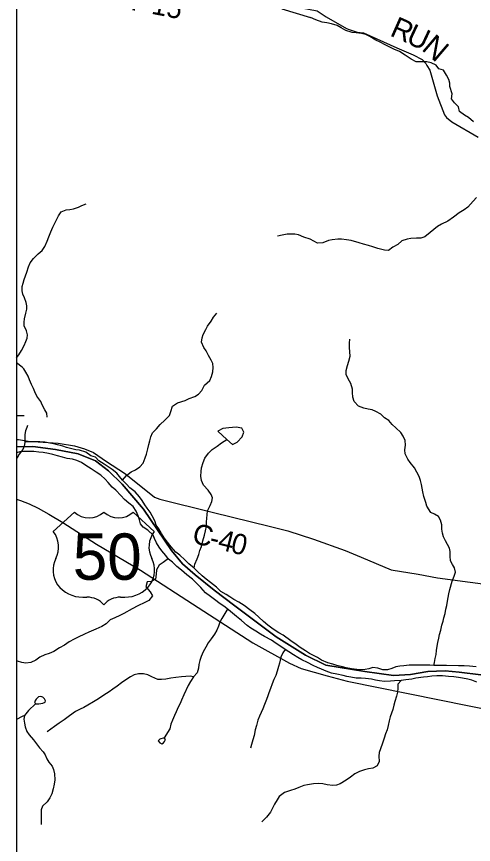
# Model space of a CAD drawing. Extents: x -139 to 835, y 0 to 440.
# Drawn here: x 373.2 to 414.4, y 270.4 to 344.8 of the extents above; entities that cross this region are included whole.
import ezdxf

# ---------------------------------------------------------------- set-up
doc = ezdxf.new("R2010")
doc.units = 0
for name, color, linetype in [('Default', 7, 'Continuous'), ('GM_X_County_Road', 7, 'Continuous'), ('GM_X_County_Road_Text', 7, 'Continuous'), ('GM_X_Major_River', 7, 'Continuous'), ('GM_X_Minor_Lake', 7, 'Continuous'), ('GM_X_Minor_River', 7, 'Continuous'), ('GM_X_Township_Road', 7, 'Continuous'), ('GM_X_Township_Road_Text', 7, 'Continuous'), ('GM_X_US_Location', 7, 'Continuous'), ('GM_X_US_Route', 7, 'Continuous'), ('GM_X_US_Shield', 7, 'Continuous'), ('SH_Cut_Line', 7, 'Continuous')]:
    doc.layers.add(name, color=color, linetype=linetype)

msp = doc.modelspace()

# ---------------------------------------------------------------- linework, layer by layer
at = {"layer": 'Default'}
for points in [[(373.24, 400.079), (373.24, 306.128), (374.696, 306.151), (376.756, 305.899), (378.796, 305.485), (380.346, 304.856), (381.503, 303.956), (382.739, 302.768), (384.674, 300.516), (387.19, 296.811), (388.165, 295.6), (389.313, 294.6), (391.035, 293.231), (392.871, 291.81), (396.601, 289.02), (399.241, 287.388), (401.077, 286.493), (404.578, 285.913), (407.16, 285.545), (408.709, 285.65), (410.258, 285.913), (411.808, 285.966), (413.07, 285.861), (415.021, 285.598)], [(415.021, 285.598), (413.07, 285.861), (411.808, 285.966), (410.258, 285.913), (408.709, 285.65), (407.16, 285.545), (404.578, 285.913), (401.077, 286.493), (399.241, 287.388), (396.601, 289.02), (392.871, 291.81), (391.035, 293.231), (389.313, 294.6), (388.165, 295.6), (387.19, 296.811), (384.674, 300.516), (382.739, 302.768), (381.503, 303.956), (380.346, 304.856), (378.796, 305.485), (376.756, 305.899), (374.696, 306.151), (373.24, 306.128), (373.24, 228.621)]]:
    msp.add_lwpolyline(points, dxfattribs=at)
at = {"layer": 'GM_X_County_Road'}
msp.add_lwpolyline([(373.24, 306.794), (373.416, 306.794), (374.294, 306.652), (376.981, 306.459), (378.441, 306.221), (379.352, 305.954), (380.168, 305.612), (381.334, 304.813), (382.959, 303.756), (384.566, 302.468), (385.652, 301.604), (386.129, 301.432), (390.834, 300.262), (396.089, 298.961), (397.653, 298.562), (399.969, 297.831), (402.806, 296.795), (404.254, 296.211), (406.971, 295.065), (409.385, 294.68), (411.116, 294.343), (416.995, 293.57)], dxfattribs=at)
at = {"layer": 'GM_X_Major_River'}
for points in [[(373.938, 308.918), (373.617, 308.91), (373.24, 308.915)], [(414.594, 286.329), (414.021, 286.384), (413.526, 286.414), (413.005, 286.432), (411.936, 286.446), (411.532, 286.451), (410.802, 286.46), (410.437, 286.476), (408.99, 286.494), (408.573, 286.476), (408.103, 286.434), (407.737, 286.378), (407.384, 286.323), (407.004, 286.195), (406.638, 286.068), (406.221, 286.073), (405.766, 286.199), (405.298, 286.265), (404.958, 286.161), (404.618, 286.094), (404.253, 286.074), (403.875, 286.079), (403.38, 286.158), (402.913, 286.248), (402.575, 286.324), (402.081, 286.462), (401.718, 286.563), (401.251, 286.701), (400.68, 286.924), (400.319, 287.157), (399.969, 287.342), (399.62, 287.538), (399.246, 287.783), (398.755, 288.077), (398.419, 288.346), (397.916, 288.664), (397.232, 289.177), (396.831, 289.398), (396.328, 289.729), (395.851, 290.095), (395.451, 290.401), (395.04, 290.802), (394.692, 291.119), (394.241, 291.473), (393.738, 291.839), (393.247, 292.158), (392.808, 292.391), (392.446, 292.636), (392.098, 292.845), (391.632, 293.103), (391.234, 293.504), (390.692, 293.919), (390.319, 294.212), (389.932, 294.506), (389.52, 294.895), (389.212, 295.199), (388.748, 295.601), (388.389, 295.954), (387.926, 296.38), (387.564, 296.649), (387.141, 297.135), (386.834, 297.559), (386.54, 297.935), (386.285, 298.334), (386.043, 298.746), (385.813, 299.073), (385.675, 299.459), (385.434, 299.918), (385.257, 300.244), (385.001, 300.596), (384.797, 300.898), (384.542, 301.31), (384.299, 301.625), (383.927, 302.074), (383.45, 302.452), (383.142, 302.756), (382.782, 303.121), (382.5, 303.449), (382.257, 303.752), (381.844, 304.094), (381.496, 304.338), (381.134, 304.559), (380.656, 304.853), (380.348, 305.193), (379.933, 305.331), (379.468, 305.637), (378.91, 305.824), (378.572, 305.864), (378.104, 305.978), (377.741, 306.079), (377.403, 306.191), (376.923, 306.317), (376.585, 306.405), (376.247, 306.469), (375.779, 306.535), (375.323, 306.565), (374.932, 306.582), (374.423, 306.576), (374.006, 306.581)], [(399.944, 286.454), (399.427, 286.736), (398.921, 286.959), (398.547, 287.18), (398.159, 287.413), (397.759, 287.67), (397.423, 287.903), (396.932, 288.233), (396.596, 288.429), (396.196, 288.723), (395.563, 289.067), (395.188, 289.276), (394.787, 289.533), (394.335, 289.815), (393.987, 290.06), (393.498, 290.498), (393.034, 290.852), (392.673, 291.157), (392.312, 291.45), (391.887, 291.791), (391.551, 292), (391.062, 292.39), (390.688, 292.671), (390.249, 293.001), (389.813, 293.475), (389.068, 294.229), (388.565, 294.619), (388.089, 295.022), (387.664, 295.351), (387.278, 295.753), (386.93, 296.033), (386.661, 296.337), (386.302, 296.762), (386.072, 297.113), (385.83, 297.5), (385.666, 297.886), (385.54, 298.188), (385.051, 298.626), (384.638, 298.884), (384.408, 299.199), (384.309, 299.572), (384.196, 299.91), (384.007, 300.332), (383.726, 300.756), (383.352, 301.049), (382.953, 301.39), (382.619, 301.743), (382.183, 302.229), (381.835, 302.497), (381.489, 302.91), (381.219, 303.213), (380.82, 303.567), (380.42, 303.848), (379.942, 304.154), (379.464, 304.448), (379.077, 304.729), (378.676, 304.902), (378.273, 305.003), (377.805, 305.069), (377.376, 305.183), (376.935, 305.32), (376.506, 305.446), (376.116, 305.535), (375.635, 305.613), (375.257, 305.641), (374.802, 305.695), (374.306, 305.701), (373.863, 305.695), (373.537, 305.675), (373.24, 305.577)], [(414.654, 284.96), (414.213, 285.134), (413.862, 285.222), (413.368, 285.312), (413.016, 285.364), (412.587, 285.418), (412.118, 285.471), (411.571, 285.514), (411.062, 285.509), (410.619, 285.478), (410.227, 285.435), (409.875, 285.403), (409.169, 285.316), (408.803, 285.225), (408.268, 285.147), (407.863, 285.105), (407.263, 285.064), (406.91, 285.045), (406.349, 285.016), (405.907, 285.057), (405.543, 285.134), (405.192, 285.21), (404.646, 285.277), (404.255, 285.306), (403.799, 285.324), (403.318, 285.402), (402.98, 285.467), (402.642, 285.555), (402.057, 285.67), (401.589, 285.749), (401.097, 285.935), (400.682, 286.108), (400.319, 286.257), (399.944, 286.454)]]:
    msp.add_lwpolyline(points, dxfattribs=at)
at = {"layer": 'GM_X_Minor_Lake'}
for points in [[(392.162, 306.791), (392.69, 306.34), (393.084, 306.551), (393.533, 307.037), (393.682, 307.455), (393.505, 307.806), (393.011, 307.908), (392.346, 307.833), (391.811, 307.768), (391.352, 307.534)], [(391.352, 307.534), (392.162, 306.791)], [(375.6, 283.589), (375.422, 283.65), (375.208, 283.629), (375.003, 283.433), (374.857, 283.189), (374.938, 282.989), (375.247, 282.997), (375.593, 283.051), (375.808, 283.165), (375.834, 283.281), (375.753, 283.458)], [(375.753, 283.458), (375.6, 283.589)], [(386.521, 279.929), (386.141, 279.826), (385.983, 279.66), (386.123, 279.49), (386.318, 279.415), (386.475, 279.485), (386.556, 279.628), (386.649, 279.783)], [(386.649, 279.783), (386.521, 279.929)]]:
    msp.add_lwpolyline(points, dxfattribs=at)
at = {"layer": 'GM_X_Minor_River'}
for points in [[(397.123, 345.53), (399.696, 344.759)], [(411.655, 340.029), (411.239, 340.131), (411.01, 340.482), (410.543, 340.68), (410.153, 340.757), (409.215, 340.769), (408.762, 341.003), (408.22, 341.37), (407.716, 341.7), (407.198, 341.923), (406.849, 342.096), (406.409, 342.293), (405.956, 342.551), (405.568, 342.725), (405.038, 343.056), (404.689, 343.216), (404.273, 343.318), (403.805, 343.384), (403.454, 343.413), (402.883, 343.588), (402.444, 343.834), (402.108, 344.043), (401.589, 344.194), (401.161, 344.272), (400.745, 344.349), (400.162, 344.549), (399.696, 344.759)], [(414.367, 335.375), (413.903, 335.765), (413.567, 335.961), (413.116, 336.303), (413.017, 336.712), (412.67, 337.076), (412.375, 337.428), (412.434, 337.883), (412.234, 338.558), (412.251, 338.858), (412.152, 339.183), (411.923, 339.582), (411.655, 340.029)], [(414.651, 328.555), (414.334, 328.235), (413.844, 327.701), (413.515, 327.441), (413.081, 327.17), (412.567, 326.793), (412.054, 326.439), (411.49, 326.158), (411.135, 325.959), (410.462, 325.403), (409.988, 325.037), (409.622, 324.91), (409.243, 324.891), (408.735, 324.862), (408.408, 324.818), (407.924, 324.668), (407.554, 324.325), (407.095, 324.079), (406.713, 323.808), (406.362, 323.812), (405.751, 323.964), (405.298, 324.114), (404.909, 324.251), (404.48, 324.377), (404.078, 324.478), (403.351, 324.68), (402.948, 324.745), (402.493, 324.799), (402.155, 324.816), (401.646, 324.763), (401.306, 324.683), (400.809, 324.498), (400.339, 324.468), (399.667, 324.801), (399.096, 325.001), (398.63, 325.199), (398.293, 325.252), (397.928, 325.257), (397.602, 325.249), (397.132, 325.184), (396.74, 325.081)], [(373.24, 314.132), (373.452, 314.413), (373.683, 314.808), (373.915, 315.238), (374.074, 315.599), (374.185, 315.902), (374.225, 316.194), (374.135, 316.569), (373.914, 317.017), (373.919, 317.345), (373.958, 317.649), (374.084, 318.162), (374.16, 318.524), (374.164, 318.816), (374.097, 319.121), (373.948, 319.533), (373.809, 319.874), (373.73, 320.168), (373.735, 320.554), (373.822, 320.857), (373.91, 321.172), (374.045, 321.521), (374.168, 321.847), (374.305, 322.337), (374.464, 322.674), (374.755, 323.08), (375.2, 323.484), (375.537, 323.795), (375.792, 324.155), (376, 324.62), (376.136, 325.016), (376.32, 325.459), (376.492, 325.878), (376.651, 326.191), (376.822, 326.564), (377.005, 326.912), (377.259, 327.26), (377.713, 327.464), (378.047, 327.495), (378.38, 327.549), (378.81, 327.695), (379.121, 327.831), (379.503, 327.978)], [(382.782, 303.121), (383.14, 303.561), (383.561, 303.867), (383.942, 304.055), (384.337, 304.338), (384.628, 304.67), (384.817, 305.124), (384.939, 305.482), (385.063, 305.961), (385.147, 306.332), (385.23, 306.667), (385.326, 307.038), (385.474, 307.384), (385.831, 307.751), (386.175, 308.143), (386.572, 308.522), (387.008, 308.948), (387.117, 309.319), (387.28, 309.797), (387.714, 310.091), (388.407, 310.31), (388.788, 310.473), (389.272, 310.659), (389.601, 310.858), (389.918, 311.202), (390.146, 311.667), (390.647, 312.105), (390.795, 312.463), (390.905, 312.881), (390.95, 313.277), (390.903, 313.626), (390.764, 313.939), (390.522, 314.351), (390.32, 314.774), (390.089, 315.077), (389.9, 315.535), (389.932, 315.931), (390.04, 316.242), (390.268, 316.683), (390.429, 316.993), (390.76, 317.42), (390.961, 317.79), (391.265, 318.146)], [(410.802, 286.46), (410.871, 286.735), (410.928, 287.094), (411.011, 287.453), (411.042, 287.813), (411.099, 288.184), (411.169, 288.519), (411.239, 288.902), (411.309, 289.237), (411.419, 289.644), (411.529, 290.086), (411.625, 290.433), (411.708, 290.744), (411.804, 291.139), (411.888, 291.51), (411.957, 291.845), (412.028, 292.228), (412.085, 292.575), (412.155, 292.91), (412.251, 293.305), (412.444, 294.047), (412.632, 294.488), (412.755, 294.859), (412.643, 295.244), (412.464, 295.546), (412.286, 295.873), (412.253, 296.281), (412.259, 296.701), (412.197, 297.002), (412.033, 297.34), (411.855, 297.678), (411.664, 298.04), (411.564, 298.366), (411.53, 298.714), (411.51, 299.122), (411.411, 299.543), (411.22, 299.846), (410.871, 300.066), (410.521, 300.215), (410.177, 300.783), (410.064, 301.12), (409.902, 301.662), (409.803, 302.084), (409.755, 302.396), (409.695, 302.745), (409.583, 303.107), (409.483, 303.456), (409.254, 303.855), (409.051, 304.229), (408.68, 304.726), (408.462, 305.029), (408.208, 305.5), (408.2, 305.872), (408.257, 306.267), (408.211, 306.7), (408.047, 307.074), (407.817, 307.413), (407.38, 307.839), (407.045, 308.143), (406.737, 308.495), (406.363, 308.74), (406.015, 309.056), (405.589, 309.314), (405.239, 309.462), (404.888, 309.527), (404.511, 309.604), (404.006, 309.779), (403.621, 310.216), (403.509, 310.589), (403.488, 311.009), (403.467, 311.322), (403.317, 311.84), (403.088, 312.239), (402.899, 312.649), (402.903, 312.997), (403.014, 313.44), (403.149, 313.822), (403.26, 314.289), (403.239, 314.673), (403.219, 315.069), (403.211, 315.465), (403.229, 315.825)], [(375.982, 308.808), (375.951, 309.148), (375.8, 309.443), (375.557, 309.914), (375.418, 310.221), (375.079, 310.682), (374.871, 311.071), (374.756, 311.376), (374.594, 311.741), (374.409, 312.153), (374.271, 312.483), (374.085, 312.848), (373.887, 313.155), (373.759, 313.309), (373.24, 313.682)], [(374.213, 308.059), (374.162, 307.873), (374.039, 307.559), (373.988, 307.231), (373.995, 306.927), (373.99, 306.517), (373.926, 306.202), (373.791, 305.876), (373.477, 305.459), (373.282, 305.134), (373.24, 305.022)], [(389.212, 295.199), (389.282, 295.57), (389.497, 296.048), (389.646, 296.43), (389.743, 296.813), (389.891, 297.159), (390.002, 297.674), (390.152, 298.164), (390.249, 298.559), (390.321, 299.002), (390.338, 299.35), (390.369, 299.697), (390.387, 300.009), (390.431, 300.381), (390.672, 300.846), (390.82, 301.204), (390.89, 301.527), (390.764, 301.853), (390.496, 302.228), (390.072, 302.678), (389.883, 303.089), (389.836, 303.485), (389.842, 303.917), (389.899, 304.229), (390.049, 304.731), (390.172, 305.113), (390.53, 305.565), (390.847, 305.873), (391.281, 306.191), (391.689, 306.485), (392.162, 306.791)], [(386.93, 296.033), (386.786, 295.975), (386.431, 295.716), (386.075, 295.468), (385.848, 295.063), (385.817, 294.679), (385.758, 294.212), (385.364, 294.013), (384.999, 293.981), (384.862, 293.527), (385.273, 293.09), (385.489, 292.715), (385.158, 292.311), (384.79, 292.124), (384.161, 291.831), (383.635, 291.55), (382.887, 291.14), (382.532, 290.952), (382.073, 290.742), (381.666, 290.567), (381.309, 290.211), (380.902, 289.964), (380.39, 289.707), (379.734, 289.439), (379.367, 289.263), (378.776, 289.007), (378.422, 288.807), (377.962, 288.573), (377.554, 288.29), (377.12, 288.043), (376.581, 287.726), (376.161, 287.527), (375.794, 287.399), (375.348, 287.213), (374.966, 286.941), (374.52, 286.719), (374.076, 286.676), (373.725, 286.728), (373.335, 286.829), (373.24, 286.844)], [(392.312, 291.45), (392.156, 291.428), (391.889, 290.987), (391.728, 290.677), (391.541, 290.343), (391.419, 289.997), (391.258, 289.639), (391.07, 289.281), (390.765, 288.853), (390.499, 288.485), (390.272, 288.091), (390.045, 287.686), (389.856, 287.256), (389.721, 286.91), (389.651, 286.551), (389.62, 286.215), (389.51, 285.796), (389.179, 285.429), (388.886, 285.024), (388.686, 284.643), (388.309, 283.807), (388.094, 283.342), (387.959, 283.031), (387.785, 282.71), (387.61, 282.28), (387.449, 281.946), (387.273, 281.54), (387.112, 281.17), (387.041, 280.75), (386.521, 279.929)], [(397.423, 287.903), (397.21, 287.605), (397.022, 287.2), (396.897, 286.661), (396.815, 286.35), (396.705, 285.955), (396.582, 285.561), (396.395, 285.203), (396.246, 284.797), (396.084, 284.379), (395.948, 283.997), (395.813, 283.639), (395.69, 283.244), (395.555, 282.934), (395.407, 282.564), (395.246, 282.218), (395.098, 281.907), (394.949, 281.537), (394.825, 281.047), (394.716, 280.652), (394.618, 280.161), (394.508, 279.767), (394.398, 279.348), (394.302, 279.001)], [(389.179, 285.429), (388.867, 285.493), (388.463, 285.462), (388.084, 285.419), (387.588, 285.365), (387.131, 285.299), (386.687, 285.221), (386.295, 285.178), (385.957, 285.206), (385.425, 285.417), (385.05, 285.614), (384.66, 285.703), (384.204, 285.697), (383.825, 285.605), (383.496, 285.417), (383.089, 285.171), (382.694, 284.899), (382.299, 284.604), (381.904, 284.333), (381.574, 284.073), (381.088, 283.779), (380.627, 283.449), (380.154, 283.191), (379.641, 282.873), (379.299, 282.685), (378.971, 282.533), (378.538, 282.299), (377.998, 281.909), (377.523, 281.567), (377.089, 281.26), (376.641, 280.966), (375.995, 280.469)], [(407.863, 285.105), (407.558, 284.76), (407.567, 284.412), (407.535, 284.041), (407.439, 283.694), (407.276, 283.216), (407.206, 282.869), (407.11, 282.486), (407.001, 282.176), (406.879, 281.829), (406.783, 281.458), (406.673, 281.064), (406.589, 280.657), (406.454, 280.298), (406.318, 279.916), (406.182, 279.474), (405.992, 278.948), (405.871, 278.626), (405.853, 278.29), (405.872, 277.81), (405.684, 277.416), (405.303, 277.205), (404.912, 277.162), (404.545, 277.07), (404.1, 276.92), (403.693, 276.697), (403.298, 276.414), (402.903, 276.119), (402.377, 275.802), (402.037, 275.698), (401.71, 275.642), (401.203, 275.708), (400.813, 275.797), (400.383, 275.827), (399.953, 275.808), (399.417, 275.719), (399.09, 275.639), (398.658, 275.489), (398.291, 275.337), (397.885, 275.198), (397.348, 275.013), (396.887, 274.671), (396.687, 274.362), (396.447, 273.981), (396.246, 273.563), (396.085, 273.253), (395.74, 272.813), (395.317, 272.398)], [(374.938, 282.989), (374.3, 282.389), (373.949, 281.948), (373.897, 281.61), (373.94, 281.27), (374.007, 280.941), (374.179, 280.517), (374.365, 280.199), (374.776, 279.76), (375.021, 279.394), (375.301, 279.051), (375.641, 278.695), (375.828, 278.4), (375.978, 278.047), (376.152, 277.752), (376.444, 277.385), (376.571, 277.091), (376.649, 276.692), (376.678, 276.153), (376.625, 275.767), (376.548, 275.347), (376.411, 274.904), (376.24, 274.531), (375.997, 274.172), (375.588, 273.791), (375.464, 273.453), (375.455, 272.774), (375.463, 272.458), (375.447, 272.142)], [(373.949, 281.948), (373.757, 281.857), (373.24, 281.593)]]:
    msp.add_lwpolyline(points, dxfattribs=at)
at = {"layer": 'GM_X_Township_Road'}
for points in [[(383.712, 348.563), (400.286, 345.344), (401.118, 344.807), (402.94, 343.765), (403.191, 343.675)], [(403.191, 343.675), (403.882, 343.429), (404.477, 343.374), (407.48, 342.028), (408.929, 341.41), (409.74, 340.967), (410.068, 340.634), (410.154, 340.429), (410.448, 340.017), (410.602, 339.387), (411.103, 337.705), (411.742, 335.995), (411.931, 335.773), (412.415, 335.362), (414.797, 333.987)]]:
    msp.add_lwpolyline(points, dxfattribs=at)
at = {"layer": 'GM_X_US_Route'}
msp.add_lwpolyline([(373.24, 301.428), (373.588, 301.301), (374.366, 301.006), (375.196, 300.596), (376.15, 300.073), (377.415, 299.321), (380.432, 297.38), (384.387, 295.017), (389.589, 291.658), (394.51, 288.493), (397.81, 286.661), (398.867, 286.184), (401.196, 285.51), (403.005, 285.05), (419.479, 281.708)], dxfattribs=at)
at = {"layer": 'GM_X_US_Shield'}
for p, q in [((378.441, 300.243), (376.548, 298.507)), ((385.635, 298.507), (383.742, 300.243)), ((379.198, 292.601), (379.577, 292.601)), ((382.606, 292.601), (382.985, 292.601))]:
    msp.add_line(p, q, dxfattribs=at)
for centre, major_axis, start_param, end_param in [((379.766, 301.484), (1.893, 0), 3.936991, 5.487786), ((382.417, 301.484), (1.893, 0), 3.936991, 5.487786), ((374.377, 297.112), (2.65, 0), 5.838949, 6.894067), ((387.806, 297.112), (-2.65, 0), 5.672304, 6.727422), ((379.169, 295.033), (2.65, 0), 2.702327, 4.723529), ((383.014, 295.033), (2.65, 0), 4.701249, 6.722451), ((379.577, 290.864), (-1.893, 0), 3.785094, 4.712389), ((382.606, 290.864), (-1.893, 0), 4.712389, 5.639684)]:
    msp.add_ellipse(centre, major_axis=major_axis, ratio=0.917426, start_param=start_param, end_param=end_param, dxfattribs=at)
at = {"layer": 'SH_Cut_Line'}
msp.add_lwpolyline([(607.596, 213.413), (607.596, 400.079), (373.24, 400.079), (373.24, 228.621), (390.412, 227.867), (402.968, 227.036), (407.389, 226.858), (433.728, 225.419), (479.461, 222.215), (494.743, 221.147), (512.652, 220.106), (533.705, 218.461), (553.865, 217.083)], close=True, dxfattribs=at)

# ---------------------------------------------------------------- texts
at = {"layer": 'GM_X_County_Road_Text'}
for s, height, rotation, p in [('C', 1.841, 346.06164, (388.947, 297.509)), ('4', 1.84, 346.08409, (391.258, 296.936)), ('0', 1.84, 346.0835, (392.414, 296.65)), ('-', 1.84, 346.0792, (390.489, 297.127))]:
    msp.add_text(s, height=height, rotation=rotation, dxfattribs=at).set_placement(p)
at = {"layer": 'GM_X_Township_Road_Text'}
for s, height, rotation, p in [('T-15', 1.8242, 349.22035, (383.043, 345.534)), ('R', 1.9, 336.08382, (406.758, 343.163)), ('U', 1.907, 334.84418, (408.195, 342.526)), ('N', 1.972, 319.50036, (409.612, 341.881))]:
    msp.add_text(s, height=height, rotation=rotation, dxfattribs=at).set_placement(p)
at = {"layer": 'GM_X_US_Location'}
msp.add_text('50', height=0.00584, rotation=0.00001, dxfattribs=at).set_placement((379.169, 297.603))
for s, p in [('0', (381.089, 296.216)), ('/', (381.09, 296.216))]:
    msp.add_text(s, height=0.00599, dxfattribs=at).set_placement(p)
at = {"layer": 'GM_X_US_Shield'}
msp.add_text('50', height=4.1684, dxfattribs=at).set_placement((378.303, 294.164))

doc.saveas('drawing.dxf')
